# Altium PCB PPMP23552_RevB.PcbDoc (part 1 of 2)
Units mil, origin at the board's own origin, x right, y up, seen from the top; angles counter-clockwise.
Board outline 4950 x 3450 mil, 4 copper layers (Top Layer 1, Layer 2, Layer 3, Bottom Layer), stack 75.824 mil thick; 113 components, 58 nets, 311 pads, 148 vias.
Unrouted connection lines stored in the file: 10.
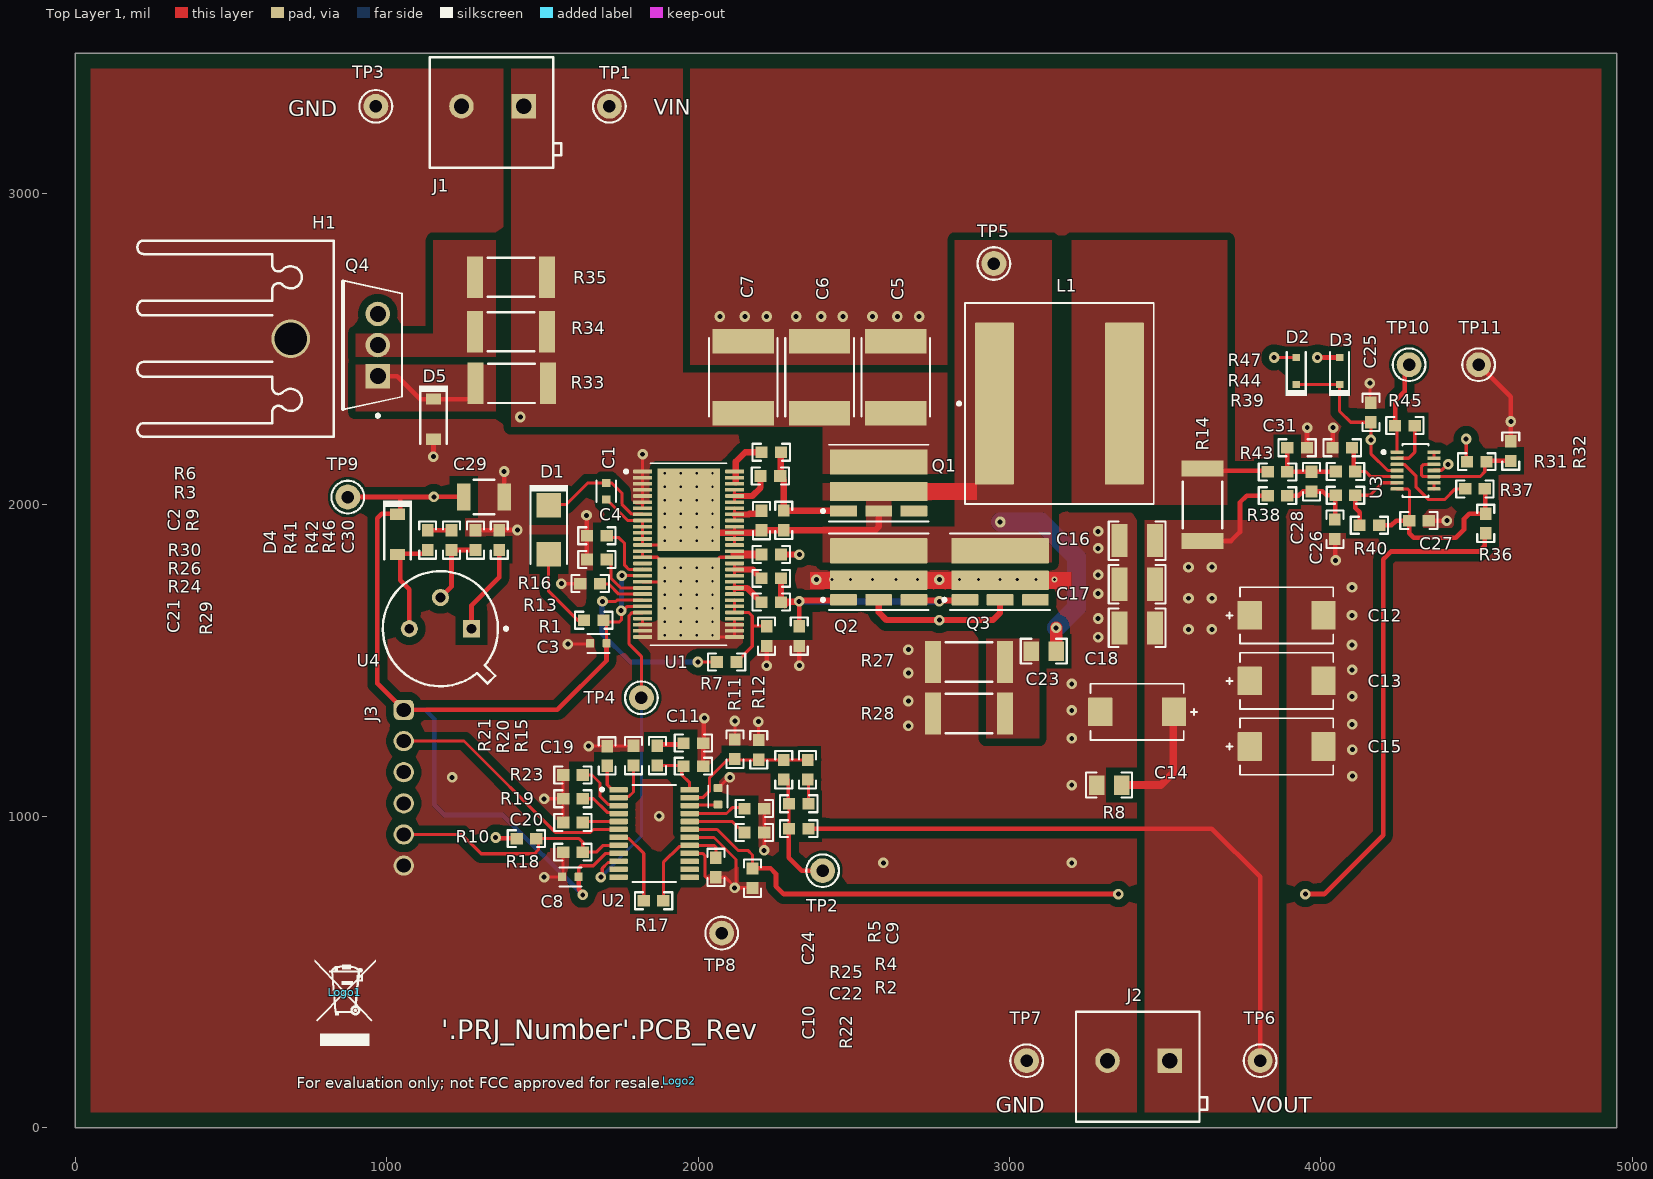
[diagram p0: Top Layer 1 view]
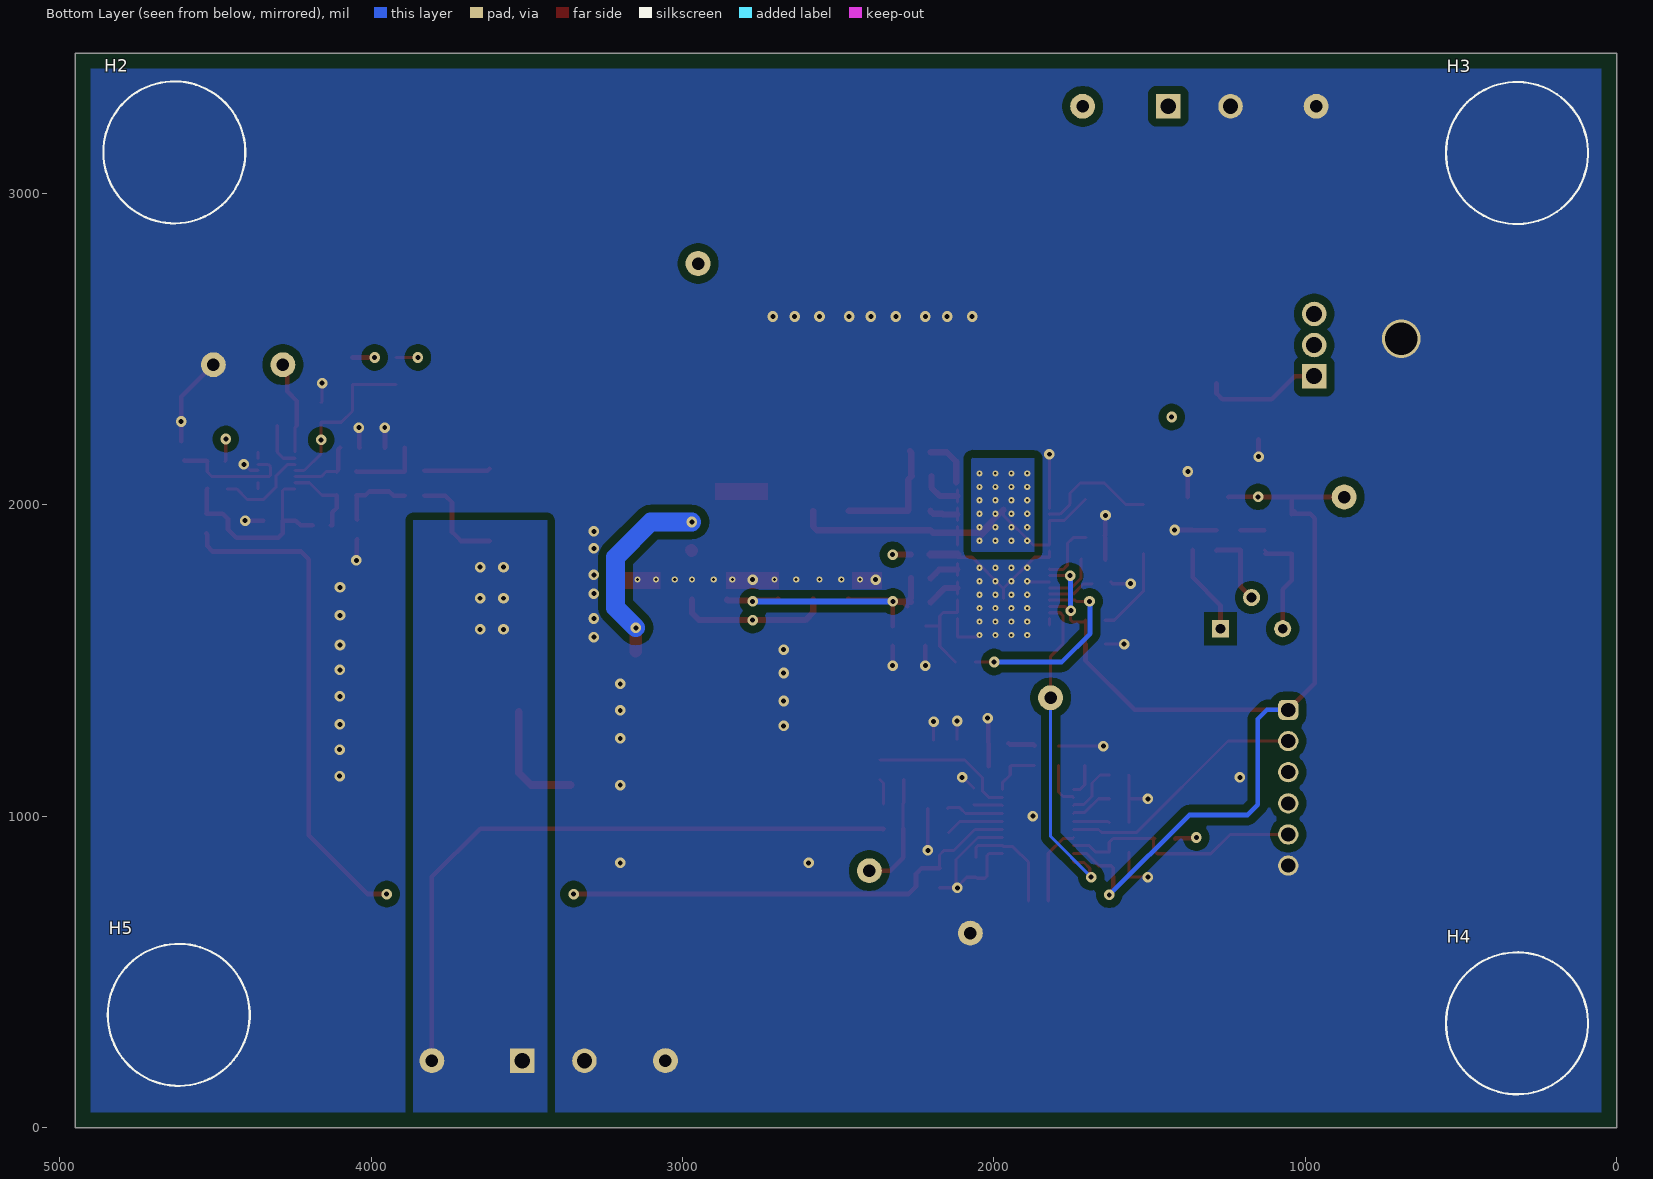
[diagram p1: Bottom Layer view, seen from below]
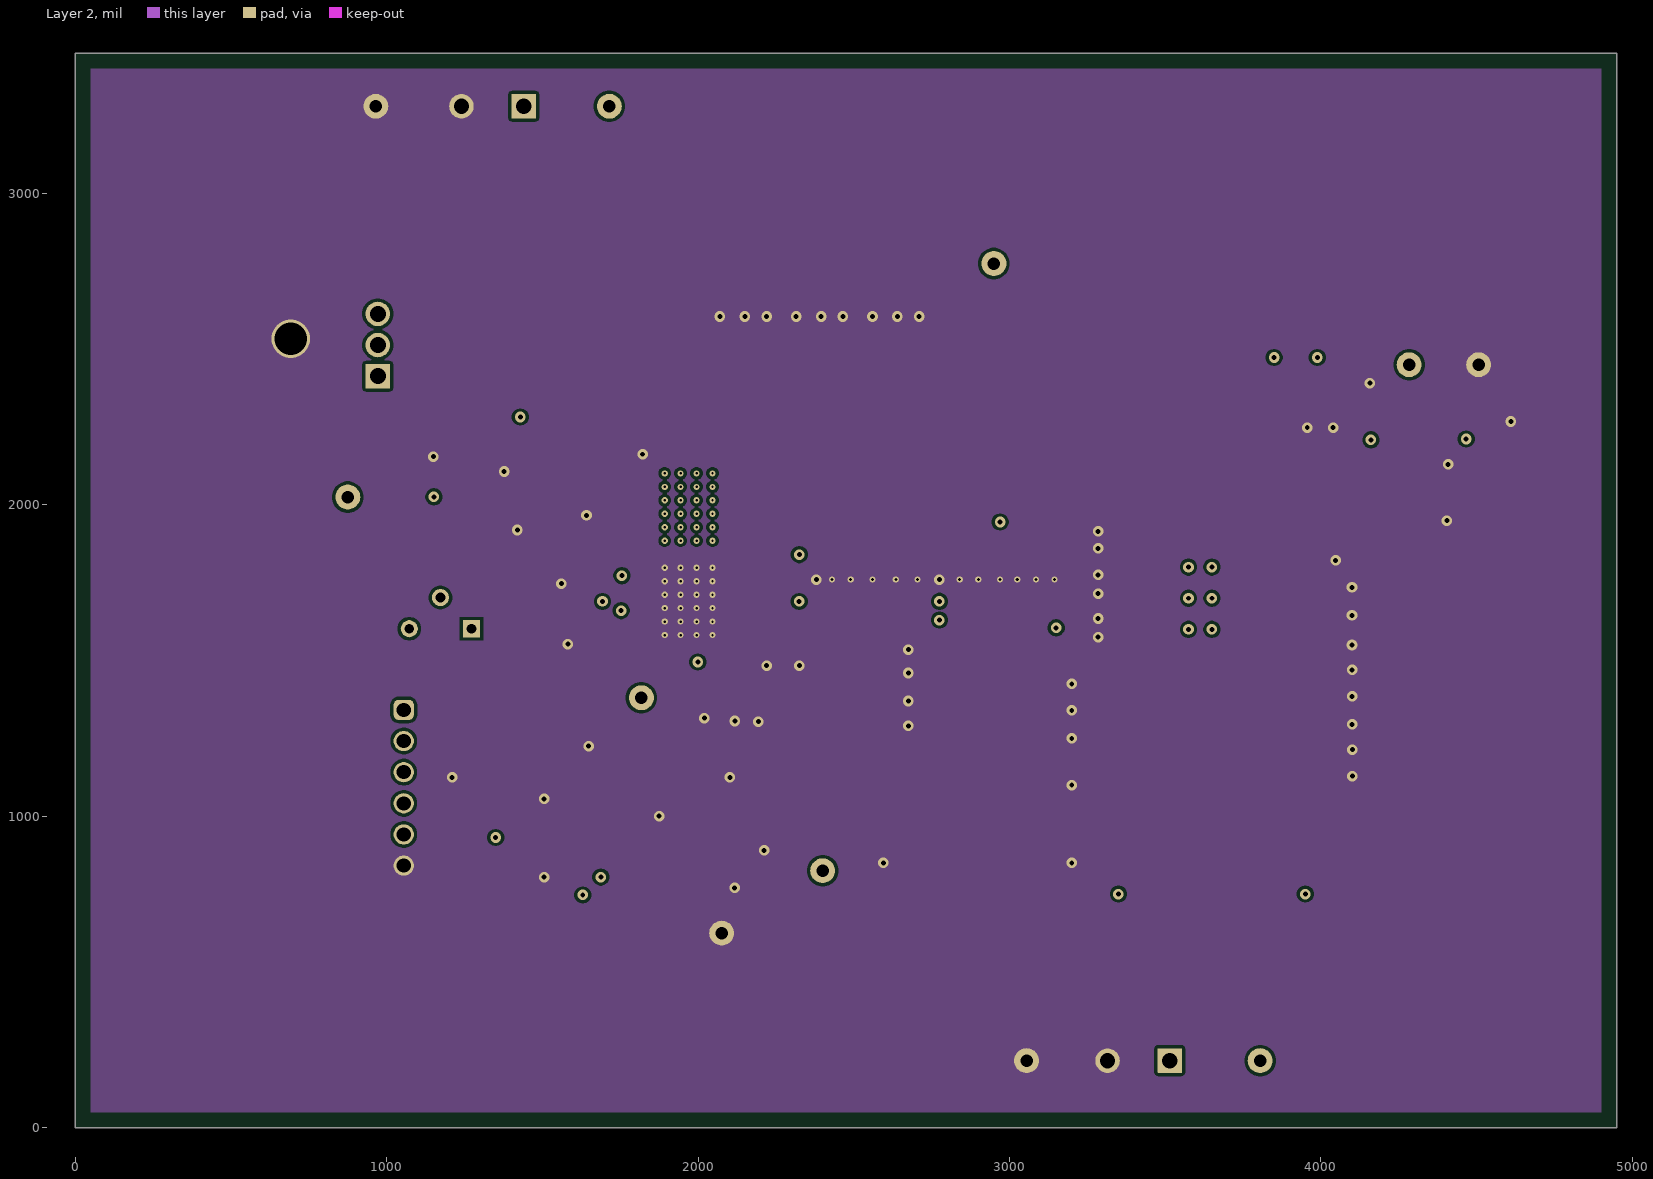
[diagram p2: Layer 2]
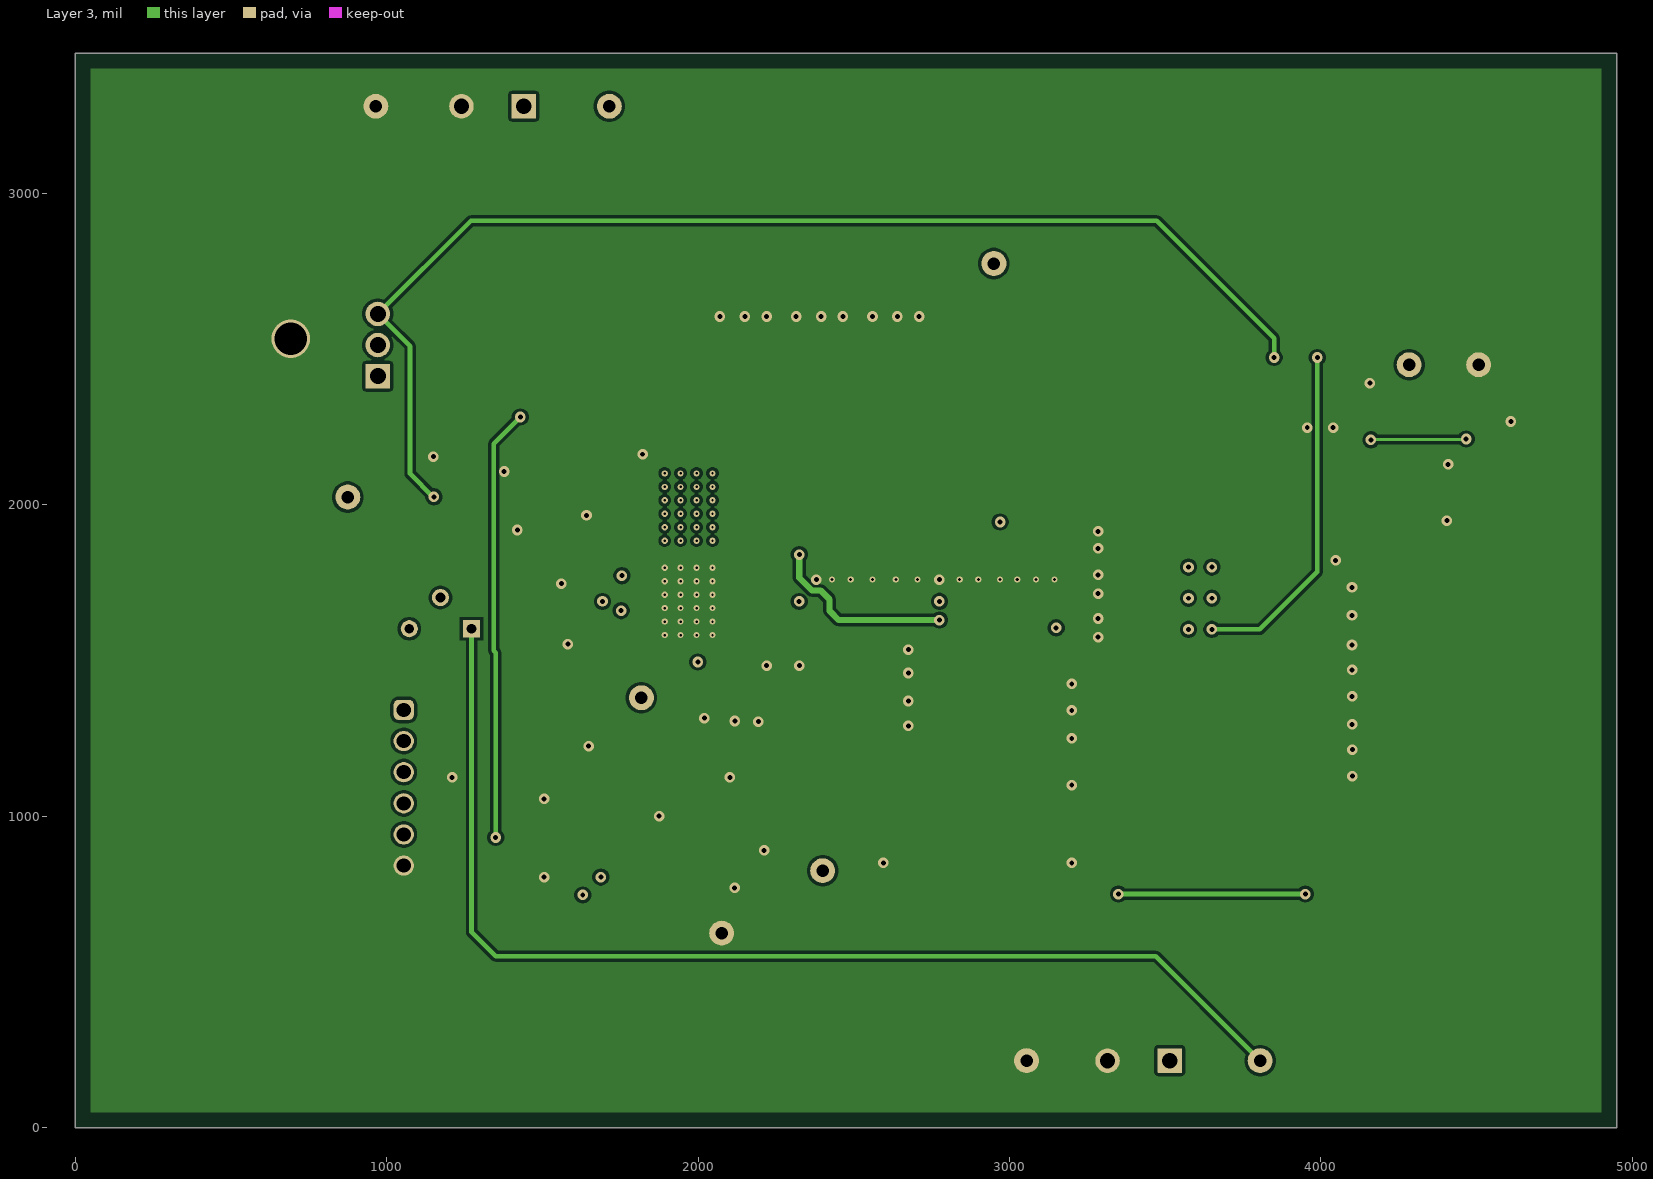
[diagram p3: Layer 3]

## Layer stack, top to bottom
Top Solder: solder mask 0.4, Solder Resist, Dk 3.5
Top Layer 1: signal copper 2.7559
Dielectric 1: prepreg 2.8, PP-006, Dk 4.1
Layer 2: signal copper 2.7559
Dielectric1: core 59.2, FR-4 High Tg, Dk 4.8
Layer 3: signal copper 2.7559
Dielectric 2: prepreg 2.8, PP-006, Dk 4.1
Bottom Layer: signal copper 2.7559
Bottom Solder: solder mask 0.4, Solder Resist, Dk 3.5

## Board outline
0,0 4950,0 4950,3450 0,3450

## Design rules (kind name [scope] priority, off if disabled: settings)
AcuteAngle [All] p1: minimum=4.50000000000000E+0001 checktracksonly=FALSE
AssemblyTestPointUsage [All] p1: valid=2
BoardOutlineClearance BoardOutlineClearance_MountingHoles [OnCopper and InComponentClass('Mounting Holes')] p1: gap=39.37 ignorepadtopadclearanceinfootprint=FALSE
BoardOutlineClearance BoardOutlineClearance_Poly [OnCopper and IsPoly] p2: gap=25 ignorepadtopadclearanceinfootprint=FALSE
BoardOutlineClearance [OnCopper and Not InComponentClass('Logo') and not InComponentClass('FiducialMark') and not InRegion(1000,500,4000,800) and not InPoly] p3: gap=40 ignorepadtopadclearanceinfootprint=FALSE
Clearance Clearance_4 [InNamedPolygon('TOP_LAYER_1_GND_P026')] p1: gap=25 ignorepadtopadclearanceinfootprint=FALSE
Clearance Clearance_3 [InNamedPolygon('BOTTOM_LAYER_GND_P023')] p2: gap=25 ignorepadtopadclearanceinfootprint=FALSE
Clearance Clearance_2 [InNamedPolygon('BOTTOM_LAYER_GND_P018')] p3: gap=25 ignorepadtopadclearanceinfootprint=FALSE
Clearance Clearance_1 [InNamedPolygon('TOP_LAYER_1_GND_P017')] p4: gap=25 ignorepadtopadclearanceinfootprint=FALSE
Clearance Clearance_Keepouts [((IsTrack Or IsArc) And Not InPoly) And IsFree and IsKeepOut vs ((IsTrack Or IsArc) And Not InPoly) And IsFree and IsKeepOut] p5: gap=0 ignorepadtopadclearanceinfootprint=FALSE
Clearance Clearance_Poly [InPolygon] p6: gap=10 ignorepadtopadclearanceinfootprint=TRUE
Clearance Clearance_FiducialMark [IsKeepOut and InComponentClass('FiducialMark') vs IsPad and InComponentClass('FiducialMark')] p7: gap=0 ignorepadtopadclearanceinfootprint=FALSE
Clearance [All] p8: gap=7.87 ignorepadtopadclearanceinfootprint=TRUE
ComponentClearance ComponentClearance_MountingHoles_FiducialMarks [InComponentClass('Mounting Holes') vs InComponentClass('FiducialMark')] p1: gap=50 collisioncheckmode=3 verticalgap=10 showdistances=FALSE
ComponentClearance ComponentClearance_Shunt [InComponentClass('Header') vs InComponentClass('Shunt')] p2: gap=0 collisioncheckmode=3 verticalgap=0 showdistances=FALSE
ComponentClearance ComponentClearance_Logo [InComponentClass('Logo')] p3: gap=30 collisioncheckmode=3 verticalgap=10 showdistances=FALSE
ComponentClearance ComponentClearance_ScrewToNut [(HasFootprint('NY PMS 440 0025 PH')) vs (HasFootprint('Keystone_1902C'))] p4: gap=5 collisioncheckmode=3 verticalgap=10 showdistances=FALSE
ComponentClearance ComponentClearance_MountingHoles [InComponentClass('Mounting Holes')] p5: gap=100 collisioncheckmode=3 verticalgap=100000 showdistances=FALSE
ComponentClearance ComponentClearance_SmallPassives [HasFootprint('0201*') or HasFootprint('0402*') or HasFootprint('0508') or HasFootprint('0603*') or HasFootprint('0612') or HasFootprint('0805*') or HasFootprint('0815*') or HasFootprint('0830*') or HasFootprint('1206*') or HasFootprint('1210*') or HasFootprint('1808*') or HasFootprint('1812*') or HasFootprint('1825*') or HasFootprint('2010*') or HasFootprint('2220*') or HasFootprint('2225*') or HasFootprint('2512*') or HasFootprint('2728*') or HasFootprint('3518*') vs HasFootprint('0201*') or HasFootprint('0402*') or HasFootprint('0508') or HasFootprint('0603*') or HasFootprint('0612') or HasFootprint('0805*') or HasFootprint('0815*') or HasFootprint('0830*') or HasFootprint('1206*') or HasFootprint('1210*') or HasFootprint('1808*') or HasFootprint('1812*') or HasFootprint('1825*') or HasFootprint('2010*') or HasFootprint('2220*') or HasFootprint('2225*') or HasFootprint('2512*') or HasFootprint('2728*') or HasFootprint('3518*')] p6: gap=14.96 collisioncheckmode=3 verticalgap=10 showdistances=FALSE
ComponentClearance ComponentClearance_THtoSMT [IsThruComponent vs IsSMTComponent] p7: gap=30 collisioncheckmode=3 verticalgap=30 showdistances=FALSE
ComponentClearance ComponentClearance_THtoTH [IsThruComponent vs IsThruComponent] p8: gap=20 collisioncheckmode=3 verticalgap=30 showdistances=FALSE
ComponentClearance [All] p9: gap=20 collisioncheckmode=3 verticalgap=10 showdistances=FALSE
DiffPairsRouting [All] p1: maxlimit=100 minlimit=10 mostfreqgap=10 toplayer_minwidth=15 toplayer_maxwidth=15 toplayer_prefwidth=15 midlayer1_minwidth=15 midlayer1_maxwidth=15 midlayer1_prefwidth=15 midlayer2_minwidth=15 midlayer2_maxwidth=15 midlayer2_prefwidth=15 bottomlayer_minwidth=15 bottomlayer_maxwidth=15 bottomlayer_prefwidth=15 maxuncoupledlength=1000
FabricationTestPointUsage TestPointUsage [All] p1: valid=2 allowmultiple=FALSE
FabricationTestpoint Testpoint [All] p1: side=3 testpointundercomponent=TRUE minsize=40 maxsize=100 preferedsize=60 minholesize=0 maxholesize=40 preferedholesize=32 testpointgrid=1 allowsidetop=TRUE allowsidebottom=TRUE usegrid=TRUE gridtolerance=0.01
FanoutControl Fanout_LCC [IsLCC] p1: bgadir=Out bgaviamode=Centered fanoutstyle=Auto fanoutdirection=Alternating viagrid=1 // Fanout_LCC (Default Rule)
FanoutControl Fanout_BGA [IsBGA] p2: bgadir=Out bgaviamode=Centered fanoutstyle=Auto fanoutdirection=Alternating viagrid=1 // Fanout_BGA (Default Rule)
FanoutControl Fanout_Default [All] p4: bgadir=Out bgaviamode=Centered fanoutstyle=Auto fanoutdirection=Alternating viagrid=1 // Fanout_Default (Default Rule)
FanoutControl Fanout_Small [(CompPinCount < 5)] p5: bgadir=Out bgaviamode=Centered fanoutstyle=Auto fanoutdirection=OutThenIn viagrid=1 // Fanout_Small (Default Rule)
HoleSize [All] p1: absolutevalues=TRUE maxlimit=251 minlimit=7.87 maxpercent=80.000 minpercent=20.000
MinimumAnnularRing MinimumAnnularRing_ThermalPadVias [IsVia and InAnyComponent] p1: minimumring=5.91
MinimumAnnularRing [All] p2: minimumring=7.87
MinimumSolderMaskSliver MinimumSolderMaskSliver_Logo [InComponentClass('Logo') vs InComponentClass('Logo')] p1: minsoldermaskwidth=0.7
MinimumSolderMaskSliver [All] p2: minsoldermaskwidth=3.94
PlaneConnect [All] p1: planeconnectstyle=Relief reliefexpansion=10 reliefentries=4 reliefconductorwidth=10 reliefairgap=10
PolygonConnect [All] p1: connectstyle=Direct reliefconductorwidth=10 reliefentries=4 polygonreliefangle="90 Angle" airgapwidth=10
RoutingVias ThermalPadVias [IsVia and InAnyComponent] p1: holewidth=7.87 width=19.68 viastyle="Through Hole" minholewidth=7.87 minwidth=19.68 maxholewidth=12.99 maxwidth=23.62
RoutingVias [All] p2: holewidth=16 width=34 viastyle="Through Hole" minholewidth=7.87 minwidth=24 maxholewidth=40 maxwidth=65
SilkToBoardRegionClearance [Not ((IsComment or IsDesignator) And (Hide <> 'False')) and not InRegion(1000,500,4000,800)] p1:
SilkToSilkClearance SilkToSilkClearance_Pb-FreeLogo [(HasFootprint('Pb-Free_Overlay_Medium') OR HasFootprint('Pb-Free_Overlay_Small')) vs (HasFootprint('Pb-Free_Overlay_Medium') OR HasFootprint('Pb-Free_Overlay_Small'))] p1: silktosilkclearance=0
SilkToSilkClearance [All] p2: silktosilkclearance=3.94
SilkToSolderMaskClearance SilkToComponentPadClearance [(IsPad or IsFill or IsRegion) and InAnycomponent] p1: minsilkscreentomaskgap=5 clearancetoexposedcopper=TRUE
SilkToSolderMaskClearance "Silk to Solder Mask Opening" [All] p2: minsilkscreentomaskgap=3.94 clearancetoexposedcopper=FALSE
SolderMaskExpansion [All] p1: expansion=1.97 istentingtop=FALSE
UnRoutedNet [All] p1: checkbadconnections=TRUE
Width [All] p1: maxlimit=100 minlimit=6 preferedwidth=10 checkconnectedcopper=TRUE
14 further rules are at their usual default settings.

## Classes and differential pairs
component class Header: J3

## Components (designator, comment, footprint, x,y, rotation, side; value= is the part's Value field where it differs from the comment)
C1 "GCJ188R71E104KA12D" FP-GCJ188R71E104KA12D_0603-MFG 1705.39,2043.54 r270 top value=100nF
C2 "885012206026" 0603 2203.58,1949.62 r90 top value=1uF
C3 "GCJ188R71E104KA12D" FP-GCJ188R71E104KA12D_0603-MFG 1680,1555 r0 top value=100nF
C4 "885012206026" 0603 1675.08,1900.78 r180 top value=1uF
C5 "CKG57NX7T2E335M500JH" CKG57N 2635,2410 r90 top value=3.3uF
C6 "CKG57NX7T2E335M500JH" CKG57N 2390,2410 r90 top value=3.3uF
C7 "CKG57NX7T2E335M500JH" CKG57N 2145,2410 r90 top value=3.3uF
C8 "GCJ188R71E104KA12D" FP-GCJ188R71E104KA12D_0603-MFG 1590,805 r0 top value=100nF
C9 "C0603X102K5RACTU" 0603 2351.65,1149.21 r90 top value=1000pF
C10 "885012206026" 0603 2057.09,835.39 r270 top value=1uF
C11 "C0603C223K5RACTU" 0603 1985,1234.85 r180 top value=0.022uF
C12 "T521X226M063ATE075" FP-T521X226M063ATE075_2917-MFG 3890,1645 r180 top value=22µF
C13 "T521X226M063ATE075" FP-T521X226M063ATE075_2917-MFG 3890,1434.44 r180 top value=22µF
C14 "T521X226M063ATE075" FP-T521X226M063ATE075_2917-MFG 3410,1335 r0 top value=22µF
C15 "T521X226M063ATE075" FP-T521X226M063ATE075_2917-MFG 3890,1223.88 r180 top value=22µF
C16 "GXM32ER71H106KA10" 1210 3410,1885 r180 top value=10uF
C17 "GXM32ER71H106KA10" 1210 3410,1745 r180 top value=10uF
C18 "GXM32ER71H106KA10" 1210 3410,1605 r180 top value=10uF
C19 "GCM1885C1H680JA16D" 0603 1985,1160.79 r180 top value=68pF
C20 "885012206086" 0603 1598.09,979.61 r180 top value=3300pF
C21 "885012206026" 0603 2220,1578.38 r90 top value=1uF
C22 "CGA3E3X7R1H474K080AE" 0603 2180.84,947.88 r0 top value=0.47uF
C23 "08052A331JAT2A" 0805_HV 3110,1530 r0 top value=330pF
C24 "GCJ188R71E104KA12D" FP-GCJ188R71E104KA12D_0603-MFG 2063.88,1063.96 r270 top value=100nF
C25 "CGA3E1X7R1V105K080AE" 0603 4160.78,2296.68 r270 top value=1uF
C26 "C0603C101F5GACTU" 0603 4045.15,1921.5 r90 top value=100pF
C27 "C0603C101F5GACTU" 0603 4315,1949.37 r0 top value=100pF
C28 "C0603C101F5GACTU" 0603 3970,2074.37 r90 top value=100pF
C29 "C1210C475K5RACAUTO" 1210_280 1312.33,2025 r0 top value=4.7uF
C30 "HMK107B7104KAHT" 0603 1361.57,1886.72 r90 top value=0.1uF
C31 "C0603C101F5GACTU" 0603 3923.77,2183.52 r0 top value=100pF
D1 "SS1200-LTP" SMA 1520.02,1919.69 r270 top value=200V
D2 "PMEG6010CEJ,115" SOD-323F 3920.76,2430.01 r90 top value=60V
D3 "PMEG6010CEJ,115" SOD-323F 4060.15,2430.01 r90 top value=60V
D4 "BAT54T1G" SOD-123 1034.75,1905.42 r270 top value=30V
D5 "MMSZ4698T1G" SOD-123 1150,2275 r270 top value=11V
H1 "V7700W" ASMN_V7700W 691.65,2533.79 r90 top
H2 "SJ-5303 (CLEAR)" Bumpon_SJ5003Transparent 4632,3132 r180 bottom
H3 "SJ-5303 (CLEAR)" Bumpon_SJ5003Transparent 320,3130 r180 bottom
H4 "SJ-5303 (CLEAR)" Bumpon_SJ5003Transparent 320,335 r180 bottom
H5 "SJ-5303 (CLEAR)" Bumpon_SJ5003Transparent 4618,362 r180 bottom
J1 "ED120/2DS" On-Shore_ED120_2DS 1340,3280 r180 top
J2 "ED120/2DS" On-Shore_ED120_2DS 3415,215 r180 top
J3 "61300611121" WURTH_61300611121 1054.75,1091.4 r270 top
L1 "XAL1513-153MED" FP-XAL1513-153MED_SMT_IND_15MM2_16MM2-MFG 3160,2325 r0 top value=15uH
Logo1 "WEEE logo" WEEE_Minimum 865,435 r0 top
Logo2 "FCC disclaimer" FCC_disclaimer 1939.2,150 r0 top
Q1 "EPC7020GSH" FP-EPC7020GSH_FSMD-G-MFG 2580,2070 r180 top
Q2 "EPC7020GSH" FP-EPC7020GSH_FSMD-G-MFG 2580,1785 r180 top
Q3 "EPC7020GSH" FP-EPC7020GSH_FSMD-G-MFG 2970,1785 r180 top
Q4 "BUX85G" FP-BUX85G_TO-220-3-MFG 954.38,2513.19 r180 top value=450V
R1 "RC0603FR-07100RL" 0603 1664.96,1629.22 r180 top value=100
R2 "RC0603FR-0710RL" 0603 2323.15,960.05 r0 top value=10.0
R3 "RC0603FR-071RL" 0603 2232.12,2092.54 r0 top value=1.00
R4 "RC0603FR-07511RL" 0603 2323.15,1040.06 r180 top value=511
R5 "RC0603FR-0749K9L" 0603 2275.15,1149.21 r270 top value=49.9k
R6 "RC0603FR-071RL" 0603 2235.07,2168.98 r0 top value=1.00
R7 "M55342K12B10E0T" 0603 2091.54,1495.3 r0 top value=10.0k
R8 "CRCW080527K0JNEA" 0805_HV 3320,1100 r180 top value=27k
R9 "M55342K12B10E0T" 0603 2275,1950 r90 top value=10.0k
R10 "RC0603FR-07562KL" 0603 1448.81,928.01 r180 top value=562k
R11 "RC0603FR-073K01L" 0603 2118.25,1215.16 r270 top value=3.01k
R12 "RC0603FR-071K78L" 0603 2194.69,1213.2 r270 top value=1.78k
R13 "RC0603FR-0712K7L" 0603 1653.43,1746.93 r0 top value=12.7k
R14 "ERJ-M1WSF4M0U" 2512 3620,2000 r270 top value=0.004
R15 "RC0603FR-072K8L" 0603 1869.33,1194.5 r90 top value=2.80k
R16 "ERJ-3EKF2002V" 0603 1675.08,1824.28 r0 top value=20.0k
R17 "RMCF0603ZT0R00" 0603 1856.94,728.53 r0 top value=0
R18 "M55342K12B10E0T" 0603 1598.09,884.48 r0 top value=10.0k
R19 "M55342K12B10E0T" 0603 1598.09,1056.05 r180 top value=10.0k
R20 "M55342K12B10E0T" 0603 1792.56,1194.5 r90 top value=10.0k
R21 "RC0603FR-07422KL" 0603 1707.91,1193.51 r270 top value=422k
R22 "RC0603FR-07100KL" 0603 2174.88,800.94 r90 top value=100k
R23 "M55342K12B10E0T" 0603 1598.09,1132.48 r180 top value=10.0k
R24 "RC0603FR-071RL" 0603 2235.07,1687.53 r0 top value=1.00
R25 "RC0603FR-07100KL" 0603 2180.84,1024.38 r180 top value=100k
R26 "RC0603FR-071RL" 0603 2235.07,1763.96 r0 top value=1.00
R27 "CRCW251220R0JNEG" 2512 2870,1495 r180 top value=20
R28 "CRCW251220R0JNEG" 2512 2870,1330 r180 top value=20
R29 "M55342K12B10E0T" 0603 2325,1578.38 r90 top value=10.0k
R30 "RMCF0603ZT0R00" 0603 2235.07,1840.47 r180 top value=0
R31 "RC0603FR-0710ML" 0603 4500.85,2138.62 r0 top value=10.0Meg
R32 "RC0603FR-0710ML" 0603 4610,2172.62 r270 top value=10.0Meg
R33 "CRCW251251K0JNEG" 2512 1401.14,2390 r180 top value=51k
R34 "CRCW25122K00FKEG" 2512 1399.04,2555.63 r0 top value=2.00k
R35 "CRCW25122K00FKEG" 2512 1399,2730.63 r0 top value=2.00k
R36 "RMCF0603ZT0R00" 0603 4529.45,1940.2 r90 top value=0
R37 "RMCF0603ZT0R00" 0603 4495,2051.26 r180 top value=0
R38 "RG1608P-103-B-T5" 0603 3860.78,2029.43 r0 top value=10.0k
R39 "RG1608P-103-B-T5" 0603 4079.15,2030.65 r0 top value=10.0k
R40 "RT0603BRD07200KL" 0603 4156,1934.38 r0 top value=200k
R41 "RC0603FR-0715RL" 0603 1131.48,1886.72 r270 top value=15.0
R42 "RC0603FR-07274RL" 0603 1207.92,1886.72 r270 top value=274
R43 "RG1608P-103-B-T5" 0603 3860.78,2105.87 r0 top value=10.0k
R44 "RG1608P-103-B-T5" 0603 4079.15,2107.09 r0 top value=10.0k
R45 "RMCF0603ZT0R00" 0603 4270,2254.37 r0 top value=0
R46 "RC0603FR-072K43L" 0603 1285.07,1886.72 r270 top value=2.43k
R47 "RT0603BRD07200KL" 0603 4068.54,2183.52 r0 top value=200k
TP1 "5000" Keystone5000 1715,3280 r90 top
TP2 "5002" Keystone5002 2400,825 r90 top
TP3 "5001" Keystone5001 965,3280 r90 top
TP4 "5002" Keystone5002 1817.92,1380.4 r90 top
TP5 "5000" Keystone5000 2950,2775 r180 top
TP6 "5000" Keystone5000 3805,215 r90 top
TP7 "5001" Keystone5001 3055,215 r90 top
TP8 "5001" Keystone5001 2075.79,624.6 r90 top
TP9 "5000" Keystone5000 875,2025 r90 top
TP10 "5000" Keystone5000 4283.5,2450 r180 top
TP11 "5001" Keystone5001 4506.75,2450 r180 top
U1 "TPS7H6005MDCATSEP" DCA0056M-MFG 1969.49,1841.35 r0 top
U2 "TPS7H5006MPWTSEP" PW0024A-MFG 1858.75,944.66 r0 top
U3 "OPA4H199MDYYTSEP" DYY0014A-MFG 4304.06,2110.32 r0 top
U4 "LM117HRLQMLV" NDT0003A 1172.47,1602.15 r180 top

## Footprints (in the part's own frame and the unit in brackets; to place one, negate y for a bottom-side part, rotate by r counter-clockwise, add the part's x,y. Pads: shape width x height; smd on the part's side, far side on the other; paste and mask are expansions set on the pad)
0603 [mm] "0603 from SM-752 data"
  rect 1x0.95 smd: 1(-0.8,0) 2(0.8,0)
  silkscreen extent -1.52,-0.69 1.52,0.69, body extent -0.87,-0.47 0.87,0.47, height 1
0805_HV [mil] "0805 with 30mil clearance between pads"
  rect 50x63 smd: 1(-40,0) 2(40,0)
  silkscreen extent -74,-40 74,40, body extent -43,-29 43,29, height 57
1210 [mm] "1210 from SM-752 data"
  rect 1.3x2.7 smd: 1(-1.45,0) 2(1.45,0)
  silkscreen extent -2.32,-1.57 2.32,1.57, body extent -1.7,-1.35 1.7,1.35, height 1.35
1210_280 [mm] "SMD, 2-Leads, Body 3.6x2.8mm, Height 2.8mm"
  rect 1.1x2.2 smd: 1(-1.65,0) 2(1.65,0)
  silkscreen extent -0.84,-1.4 0.84,1.4, body extent -1.8,-1.4 1.8,1.4, height 2.8
2512 [mm] "Chip Resistor, Body 6.3x3.2mm, IPC Medium Density"
  rect 1.3x3.4 smd: 1(-2.95,0) 2(2.95,0)
  silkscreen extent -1.9,-1.6 1.9,1.6, body extent -3.22,-1.67 3.22,1.67, height 0.71
ASMN_V7700W [mm] "Heat Sink SOT-32, TO-220"
  round 3.15 hole 2.65: 1(0,0)
  silkscreen extent -8,-3.5 8,12.5, body extent -8,-3.5 8,12.5, height 25
Bumpon_SJ5003Transparent [mil] "3M Hemispherical Bumpon transparent"
  round 1 on Mech4: 0(0,0)
  silkscreen extent -228,-228 228,228, body extent -218,-218 219,218, height 197
CKG57N [mm] "Chip Capacitor, Body 6.0x5.0x5.0mm,"
  rect 2x5 smd: 1(-2.95,0) 2(2.95,0)
  silkscreen extent -3.2,-2.8 3.2,2.8, body extent -3.3,-2.75 3.3,2.75, height 5.5
DCA0056M-MFG [mm]
  rrect33% 1.55x0.3 smd paste+0 mask+0: 1(-3.75,6.75) 2(-3.75,6.25) 3(-3.75,5.75) 4(-3.75,5.25) 5(-3.75,4.75) 6(-3.75,4.25) 7(-3.75,3.75) 8(-3.75,3.25) 9(-3.75,2.75) 10(-3.75,2.25) 11(-3.75,1.75) 12(-3.75,1.25) 13(-3.75,0.75) 14(-3.75,0.25) 15(-3.75,-0.25) 16(-3.75,-0.75) 17(-3.75,-1.25) 18(-3.75,-1.75) 19(-3.75,-2.25) 20(-3.75,-2.75) 21(-3.75,-3.25) 22(-3.75,-3.75) 23(-3.75,-4.25) 24(-3.75,-4.75) 25(-3.75,-5.25) 26(-3.75,-5.75) 27(-3.75,-6.25) 28(-3.75,-6.75) 29(3.75,-6.75) 30(3.75,-6.25) 31(3.75,-5.75) 32(3.75,-5.25) 33(3.75,-4.75) 34(3.75,-4.25) 35(3.75,-3.75) 36(3.75,-3.25) 37(3.75,-2.75) 38(3.75,-2.25) 39(3.75,-1.75) 40(3.75,-1.25) 41(3.75,-0.75) 42(3.75,-0.25) 43(3.75,0.25) 44(3.75,0.75) 45(3.75,1.25) 46(3.75,1.75) 47(3.75,2.25) 48(3.75,2.75) 49(3.75,3.25) 50(3.75,3.75) 51(3.75,4.25) 52(3.75,4.75) 53(3.75,5.25) 54(3.75,5.75) 55(3.75,6.25) 56(3.75,6.75)
  rrect2% 5.1x6.75 smd paste-1000 mask-1000: 57(0,3.625) 58(0,-3.625)
  silkscreen extent -5.22,-7.42 3.1,7.42, body extent -4.62,-7.15 4.62,7.15, height 0.25
DYY0014A-MFG [mm]
  rrect33% 1.05x0.3 smd paste+0 mask+0: 1(-1.5,1.5) 2(-1.5,1) 3(-1.5,0.5) 4(-1.5,0) 5(-1.5,-0.5) 6(-1.5,-1) 7(-1.5,-1.5) 8(1.5,-1.5) 9(1.5,-1) 10(1.5,-0.5) 11(1.5,0) 12(1.5,0.5) 13(1.5,1) 14(1.5,1.5)
  silkscreen extent -2.72,-2.15 1.05,2.15, body extent -1.63,-2.1 1.63,2.1, height 1.1
FCC_disclaimer [mil]
FP-BUX85G_TO-220-3-MFG [mm]
  rrect5% 2x2 hole 1.3 paste-1000 mask+0: 1(-0.433,2.54)
  round 2 hole 1.3 paste-1000 mask+0: 2(-0.433,0) 3(-0.433,-2.54)
  silkscreen extent -2.41,-5.27 2.41,5.89, body extent -2.51,-5.37 2.51,5.37, height 0.25
FP-EPC7020GSH_FSMD-G-MFG [mm]
  rrect11% 2.184x0.914 smd paste+0 mask+0: 1(2.87,2.286) 2(-2.87,2.286) 5(0,2.286)
  rrect5% 7.95x2.057 smd paste+0 mask+0: 3(0,-1.714)
  rrect6% 7.95x1.575 smd paste+0 mask+0: 4(0,0.686)
  silkscreen extent -4.08,-3.13 4.67,3.13, body extent -4.18,-2.96 4.18,2.96, height 0.25
FP-GCJ188R71E104KA12D_0603-MFG [mm]
  rrect15% 0.65x0.7 smd paste+0 mask+0: 1(-0.675,0) 2(0.675,0)
  silkscreen extent -0.9,-0.79 0.9,0.77, body extent -0.8,-0.4 0.8,0.4, height 0.9
FP-T521X226M063ATE075_2917-MFG [mm] "Recommended Land Pattern"
  rrect5% 1.99x2.33 smd paste+0 mask+0: 1(-3.01,0) 2(3.01,0)
  silkscreen extent -3.8,-2.3 4.9,2.3, body extent -4.13,-2.42 4.13,2.42, height 0.25
FP-XAL1513-153MED_SMT_IND_15MM2_16MM2-MFG [mm]
  rrect3% 3.18x13.2 smd paste+0 mask+0: 1(-5.3,0) 2(5.3,0)
  silkscreen extent -8.3,-8.2 7.7,8.2, body extent -7.8,-8.3 7.8,8.3, height 0.25
Keystone5000 [mil] "For Keystone 500x miniature loop terminals"
  round 80 hole 40: 1(0,0)
  silkscreen extent -52,-52 52,52, body extent -49,-49 49,49, height 182
Keystone5001 [mil] "For Keystone 500x miniature loop terminals"
  round 80 hole 40: 1(0,0)
  silkscreen extent -52,-52 52,52, body extent -49,-49 49,49, height 182
Keystone5002 [mil] "For Keystone 500x miniature loop terminals"
  round 80 hole 40: 1(0,0)
  silkscreen extent -52,-52 52,52, body extent -49,-49 49,49, height 182
NDT0003A [mm] "Can; 3 Leads; Pin Circle Dia. 5.08 mm; Lead Dia. 0.48 mm (max)"
  rect 1.4x1.4 hole 0.8: 1(-2.54,0)
  round 1.4 hole 0.8: 2(0,-2.54) 3(2.54,0)
  silkscreen extent -5.48,-4.69 4.69,4.69, body extent -4.69,-4.69 4.69,4.69, height 4.7
On-Shore_ED120_2DS [mm] "ONSHORE"
  rrect5% 2x2 hole 1.25: 1(-2.54,0)
  round 2 hole 1.25: 2(2.54,0)
  silkscreen extent -5.6,-4 5.12,5, body extent -5.78,-4 5.08,5, height 13
PW0024A-MFG [mm]
  rrect22% 1.5x0.45 smd paste+0 mask+0: 1(-2.9,3.575) 2(-2.9,2.925) 3(-2.9,2.275) 4(-2.9,1.625) 5(-2.9,0.975) 6(-2.9,0.325) 7(-2.9,-0.325) 8(-2.9,-0.975) 9(-2.9,-1.625) 10(-2.9,-2.275) 11(-2.9,-2.925) 12(-2.9,-3.575) 13(2.9,-3.575) 14(2.9,-2.925) 15(2.9,-2.275) 16(2.9,-1.625) 17(2.9,-0.975) 18(2.9,-0.325) 19(2.9,0.325) 20(2.9,0.975) 21(2.9,1.625) 22(2.9,2.275) 23(2.9,2.925) 24(2.9,3.575)
  silkscreen extent -4.37,-3.95 1.78,3.95, body extent -3.75,-4.2 3.75,4.2, height 0.25
SMA [mm] "Molded Diode, 2-Leads, Body 4.3x2.6mm, IPC Medium Density, based on OnSemi component dimensions and land pattern"
  rect 2x2 smd: 1(-2,0) 2(2,0)
  silkscreen extent -3.66,-1.57 2.79,1.57, body extent -2.6,-1.3 2.6,1.3, height 2.42
SOD-123 [mm] "On Semi recommended land pattern"
  rect 0.915x1.22 smd: 1(-1.637,0) 2(1.637,0)
  silkscreen extent -2.74,-1.17 2.03,1.16, body extent -1.93,-0.9 1.93,0.9, height 1.35
SOD-323F [mm] "NXP recommended land pattern"
  rect 0.6x0.6 smd paste-0.05: 1(-1.1,0) 2(1.1,0)
  silkscreen extent -2.06,-0.86 1.53,0.86, body extent -1.35,-0.67 1.35,0.68, height 0.79
WEEE_Minimum [mil] "WEEElie bin"
  silkscreen extent -95,-172 99,104
WURTH_61300611121 [mm] "Header, 2.54mm, 6x1, TH"
  rrect50% 1.65x1.65 hole 1.15: 1(-6.35,0)
  round 1.65 hole 1.15: 2(-3.81,0) 3(-1.27,0) 4(1.27,0) 5(3.81,0) 6(6.35,0)
  body extent -7.62,-1.27 7.62,1.27, height 8.54

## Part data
C1 C3 C8 C24: library part CMP-0095670-2, "Cap Ceramic 0.1uF 25V X7R 10% Pad SMD 0603 Soft Termination +125°C Automotive T/R", Manufacturer=Murata, Operating Temperature Range="-55°C to +125°C", TempCo=15%, Temperature Characteristic=X7R, Tolerance_%=10%, ValueDisplayed=0.1uF
C2 C4 C10 C21: library part CMP-0064932-4, "CAP, CERM, 1 uF, 10 V,+/- 10%, X7R, 0603", Cap_Case=0603, Manufacturer="Wurth Elektronik", Supplier Part Number 1=732-7945-1-ND, TempCo=X7R, Tolerance_%=10%, Value1=Unknown, Value2=10V, ValueDisplayed=1uF
C5 C6 C7: library part CMP-0009427-2, "CAP, CERM, 3.3 uF, 250 V, +/- 20%, X7T, AEC-Q200 Grade 1, 6x5x5mm", Cap_Case=2220, Manufacturer=TDK, Supplier Part Number 1=445-7108-1-ND, TempCo=X7T, Tolerance_%=20%, Value1=Unknown, Value2=250V, ValueDisplayed=3.3uF
C9: library part CMP-0006976-5, "CAP, CERM, 1000 pF, 50 V, +/- 10%, X7R, 0603", Cap_Case=0603, Manufacturer=Kemet, Supplier Part Number 1=399-5348-1-ND, TempCo=X7R, Tolerance_%=10%, Value1=Unknown, Value2=50V, ValueDisplayed=1000pF
C11: library part CMP-0006901-4, "CAP, CERM, 0.022 uF, 50 V, +/- 10%, X7R, 0603", Cap_Case=0603, Manufacturer=Kemet, Supplier Part Number 1=399-1280-1-ND, TempCo=X7R, Tolerance_%=10%, Value1=Unknown, Value2=50V, ValueDisplayed=0.022uF
C12 C13 C14 C15: library part CMP-0124532-1, "Cap Tant Polymer 22uF 63VDC X CASE 20% (7.3 X 4.3 X 4mm) SMD 7343-43 0.075 Ohm 125C T/R", Digikey Part Number=399-14801-1-ND, Leakage Current=138.6uA, Manufacturer=KEMET, Mouser Part Number=80-T521X226M63ATE075, Operating Temperature Range="-55°C to +125°C", Tolerance_%=20%, ValueDisplayed=22uF
C16 C17 C18: library part CMP-0861001-1, "CAP, CERM, 10 µF, 50 V,+/- 10%, X7R, 1210", Cap_Case=1210, Manufacturer=MuRata, TempCo=X7R, Tolerance_%=10%, Value2=50V, ValueDisplayed=10µF
C19: library part CMP-0007129-4, "CAP, CERM, 68 pF, 50 V, +/- 5%, C0G/NP0, AEC-Q200 Grade 1, 0603", Cap_Case=0603, Manufacturer=MuRata, Supplier Part Number 1=490-4961-1-ND, TempCo=C0G/NP0, Tolerance_%=5%, Value1=Unknown, Value2=50V, ValueDisplayed=68pF
C20: library part CMP-0077942-1, "CAP, CERM, 3300 pF, 50 V,+/- 10%, X7R, 0603", Cap_Case=0603, Manufacturer="Wurth Elektronik", Supplier Part Number 1=732-8004-1-ND, TempCo=X7R, Tolerance_%=10%, Value2=50V, ValueDisplayed=3300pF
C22: library part CMP-0007097-4, "CAP, CERM, 0.47 uF, 50 V, +/- 10%, X7R, AEC-Q200 Grade 1, 0603", Cap_Case=0603, Manufacturer=TDK, Supplier Part Number 1=445-172475-1-ND, TempCo=X7R, Tolerance_%=10%, Value1=Unknown, Value2=50V, ValueDisplayed=0.47uF
C23: library part CMP-0080810-1, "CAP, CERM, 330 pF, 200 V,+/- 5%, C0G/NP0, 0805", Cap_Case=0805, Manufacturer=AVX, Supplier Part Number 1=478-1275-1-ND, TempCo=C0G/NP0, Tolerance_%=5%, Value2=200V, ValueDisplayed=330pF
C25: library part CMP-0081259-1, "CAP, CERM, 1 µF, 35 V,+/- 10%, X7R, AEC-Q200 Grade 1, 0603", Cap_Case=0603, Manufacturer=TDK, Supplier Part Number 1=445-174339-1-ND, TempCo=X7R, Tolerance_%=10%, Value2=35V, ValueDisplayed=1µF
C26 C27 C28 C31: library part CMP-0080091-1, "CAP, CERM, 100 pF, 50 V,+/- 1%, C0G/NP0, 0603", Cap_Case=0603, Manufacturer=Kemet, Supplier Part Number 1=399-7819-1-ND, TempCo=C0G/NP0, Tolerance_%=1%, Value2=50V, ValueDisplayed=100pF
C29: library part CMP-0079604-1, "CAP, CERM, 4.7 µF, 50 V,+/- 10%, X7R, AEC-Q200 Grade 1, 1210", Cap_Case=1210, Manufacturer=Kemet, Supplier Part Number 1=399-7049-1-ND, TempCo=X7R, Tolerance_%=10%, Value2=50V, ValueDisplayed=4.7µF
C30: library part CMP-0081011-1, "CAP, CERM, 0.1 µF, 100 V,+/- 10%, X7R, AEC-Q200 Grade 1, 0603", Cap_Case=0603, Manufacturer="Taiyo Yuden", Supplier Part Number 1=587-6009-1-ND, TempCo=X7R, Tolerance_%=10%, Value2=100V, ValueDisplayed=0.1µF
D1: library part CMP-0028981-2, "Diode, Schottky, 200 V, 1 A, SMA", Manufacturer="Micro Commercial Components", Value1=1A, Value2=0.92V
D2 D3: library part CMP-0077011-2, "Diode, Schottky, 60 V, 1 A, SOD-323F", Manufacturer=Nexperia, Value1=1A, Value2=0.66V
D4: library part CMP-0028457-2, "Diode, Schottky, 30 V, 0.2 A, SOD-123", Manufacturer="ON Semiconductor", Value1=0.2A, Value2=0.8V
D5: library part CMP-0005741-4, "Diode, Zener, 11 V, 500 mW, SOD-123", Manufacturer="ON Semiconductor", Power_W=500mW, Value1=0.5W
H1: library part CMP-0067644-1, "Heatsink SOT-32, TO-220", Manufacturer="Assman WSW", Supplier Part Number 1=AE10850-ND
H2 H3 H4 H5: library part CMP-0003620-1, "Bumpon, Hemisphere, 0.44 X 0.20, Clear", Manufacturer=3M, Supplier Part Number 1=SJ5303-7-ND
J1 J2: library part CMP-0074910-1, "Terminal Block, 5.08 mm, 2x1, Brass, TH", Color=Blue, Current_A=15A, Manufacturer="On-Shore Technology", Supplier Part Number 1=ED1609-ND, Voltage_V=300V
J3: library part CMP-0054801-2, "Header, 2.54 mm, 6x1, Gold, TH", Color=Black, Manufacturer="Wurth Elektronik", Supplier Part Number 1=732-5319-ND
L1: library part CMP-0035008-1, "Power Inductors - SMD 15uH Shld 20% 22A 7.5mOhms AECQ2", Manufacturer=Coilcraft, Mouser Part Number=994-XAL1513-153MED, Operating Temperature Range=to, Self Resonant Frequency=8MHz, Test Frequency=1MHz, Tolerance_%=20%
Logo1: library part CMP-0074769-4, Manufacturer="Texas Instruments"
Logo2: library part CMP-0074847-1, "FCC_disclaimer"
Q1 Q2 Q3: library part CMP-0120049-1, "MOSFET N-Channel 200 V 80A (Tc) Surface Mount 5-SMD", Digikey Part Number=4107-EPC7020GSH-ND, Drain To Source Breakdown Voltage=200V, Input Capacitace At Vds="1313pF @ 100V", Manufacturer="EPC Space", Operating Temperature Range="-55°C to +150°C", Pulse Drain Current=200A
Q4: library part CMP-0094657-1, "Bipolar (BJT) Transistor NPN 450 V 2 A 4MHz 50 W Through Hole TO-220", Digikey Part Number=BUX85GOS-ND, Emitter Base Voltage=5V, Manufacturer="On Semiconductor", Mouser Part Number=863-BUX85G, Operating Temperature Range="-65°C to +150°C", Power_W=50W
R1: library part CMP-0022736-4, "RES, 100, 1%, 0.1 W, 0603", Manufacturer=Yageo, Power_W=100mW, Supplier Part Number 1=311-100HRCT-ND, TempCo="100 ppm/C", Tolerance_%=1%, Value2=0.1W, Value_Code=100R, ValueDisplayed=100
R2: library part CMP-0022751-4, "RES, 10.0, 1%, 0.1 W, 0603", Manufacturer=Yageo, Power_W=100mW, Supplier Part Number 1=311-10.0HRCT-ND, TempCo="100 ppm/C", Tolerance_%=1%, Value2=0.1W, Value_Code=10R0, ValueDisplayed=10.0
R3 R6 R24 R26: library part CMP-0022900-4, "RES, 1.00, 1%, 0.1 W, 0603", Manufacturer=Yageo, Power_W=100mW, Supplier Part Number 1=311-1.00HRCT-ND, TempCo="200 ppm/C", Tolerance_%=1%, Value2=0.1W, Value_Code=1R00, ValueDisplayed=1.00
R4: library part CMP-0023165-5, "RES, 511, 1%, 0.1 W, 0603", Manufacturer=Yageo, Power_W=100mW, Supplier Part Number 1=311-511HRCT-ND, TempCo="100 ppm/C", Tolerance_%=1%, Value2=0.1W, Value_Code=511R, ValueDisplayed=511
R5: library part CMP-0023142-5, "RES, 49.9 k, 1%, 0.1 W, 0603", Manufacturer=Yageo, Power_W=100mW, Supplier Part Number 1=311-49.9KHRCT-ND, TempCo="100 ppm/C", Tolerance_%=1%, Value2=0.1W, Value_Code=49k9, ValueDisplayed=49.9k
R7 R9 R18 R19 R20 R23 R29: library part CMP-0080488-1, "RES, 10.0 k, 1%, 0.1 W, 0603", Manufacturer="TT Electronics/IRC", Power_W=100mW, TempCo="100 ppm/C", Tolerance_%=1%, Value2=0.1W, Value_Code=10k0, ValueDisplayed=10.0k
R8: library part CMP-0020508-3, "RES, 27 k, 5%, 0.125 W, AEC-Q200 Grade 0, 0805", Manufacturer=Vishay-Dale, Power_W=125mW, Supplier Part Number 1=541-27KACT-ND, TempCo="200 ppm/C", Tolerance_%=5%, Value2=0.125W, Value_Code=27k0, ValueDisplayed=27k
R10: library part CMP-0023184-4, "RES, 562 k, 1%, 0.1 W, 0603", Manufacturer=Yageo, Power_W=100mW, Supplier Part Number 1=311-562KHRCT-ND, TempCo="100 ppm/C", Tolerance_%=1%, Value2=0.1W, Value_Code=562k
R11: library part CMP-0023076-5, "RES, 3.01 k, 1%, 0.1 W, 0603", Manufacturer=Yageo, Power_W=100mW, Supplier Part Number 1=311-3.01KHRCT-ND, TempCo="100 ppm/C", Tolerance_%=1%, Value2=0.1W, Value_Code=3k01, ValueDisplayed=3.01k
R12: library part CMP-0022889-5, "RES, 1.78 k, 1%, 0.1 W, 0603", Manufacturer=Yageo, Power_W=100mW, Supplier Part Number 1=311-1.78KHRCT-ND, TempCo="100 ppm/C", Tolerance_%=1%, Value2=0.1W, Value_Code=1k78, ValueDisplayed=1.78k
R13: library part CMP-0022778-5, "RES, 12.7 k, 1%, 0.1 W, 0603", Manufacturer=Yageo, Power_W=100mW, Supplier Part Number 1=311-12.7KHRCT-ND, TempCo="100 ppm/C", Tolerance_%=1%, Value2=0.1W, Value_Code=12k7, ValueDisplayed=12.7k
R14: library part CMP-0015813-2, "RES, 0.004, 1%, 1 W, 2512", Manufacturer=Panasonic, Power_W=1W, Supplier Part Number 1=P4.0MCT-ND, TempCo="350 ppm/C", Tolerance_%=1%, Value_Code=4L000, ValueDisplayed=0.004
R15: library part CMP-0022998-5, "RES, 2.80 k, 1%, 0.1 W, 0603", Manufacturer=Yageo, Power_W=100mW, Supplier Part Number 1=311-2.80KHRCT-ND, TempCo="100 ppm/C", Tolerance_%=1%, Value2=0.1W, Value_Code=2k80, ValueDisplayed=2.80k
R16: library part CMP-0022691-3, "RES, 20.0 k, 1%, 0.1 W, AEC-Q200 Grade 0, 0603", Manufacturer=Panasonic, Power_W=100mW, Supplier Part Number 1=P20.0KHCT-ND, TempCo="100 ppm/C", Tolerance_%=1%, Value2=0.1W, Value_Code=20k0, ValueDisplayed=20.0k
R17 R30: library part CMP-0023343-3, "RES, 0, 1%, 0.1 W, AEC-Q200 Grade 0, 0603", Manufacturer="Stackpole Electronics Inc", Power_W=100mW, Supplier Part Number 1=RMCF0603ZT0R00CT-ND, TempCo=ppm/C, Tolerance_%=1%, Value2=0.1W, Value_Code=0
R21: library part CMP-0023104-4, "RES, 422 k, 1%, 0.1 W, 0603", Manufacturer=Yageo, Power_W=100mW, Supplier Part Number 1=311-422KHRCT-ND, TempCo="100 ppm/C", Tolerance_%=1%, Value2=0.1W, Value_Code=422k
R22 R25: library part CMP-0022735-5, "RES, 100 k, 1%, 0.1 W, 0603", Manufacturer=Yageo, Power_W=100mW, Supplier Part Number 1=311-100KHRCT-ND, TempCo="100 ppm/C", Tolerance_%=1%, Value2=0.1W, Value_Code=100k
R27 R28: library part CMP-0015914-3, "RES, 20, 5%, 1 W, AEC-Q200 Grade 0, 2512", Manufacturer=Vishay-Dale, Power_W=1W, Supplier Part Number 1=541-20XCT-ND, TempCo="200 ppm/C", Tolerance_%=5%, Value_Code=20R0, ValueDisplayed=20
R31 R32: library part CMP-0022747-4, "RES, 10.0 M, 1%, 0.1 W, 0603", Manufacturer=Yageo, Power_W=100mW, Supplier Part Number 1=311-10.0MHRCT-ND, TempCo="100 ppm/C", Tolerance_%=1%, Value2=0.1W, Value_Code=10M0, ValueDisplayed=10.0M
R33: library part CMP-0015977-3, "RES, 51 k, 5%, 1 W, AEC-Q200 Grade 0, 2512", Manufacturer=Vishay-Dale, Power_W=1W, Supplier Part Number 1=541-51KXCT-ND, TempCo="200 ppm/C", Tolerance_%=5%, Value_Code=51k0, ValueDisplayed=51k
R34 R35: library part CMP-0015569-3, "RES, 2.00 k, 1%, 1 W, AEC-Q200 Grade 0, 2512", Manufacturer=Vishay-Dale, Power_W=1W, Supplier Part Number 1=541-2.00KAFCT-ND, TempCo="100 ppm/C", Tolerance_%=1%, Value_Code=2k00, ValueDisplayed=2.00k
R36 R37 R45: library part CMP-0023343-2, "RES, 0, 1%, 0.1 W, AEC-Q200 Grade 0, 0603", Manufacturer="Stackpole Electronics Inc", Power_W=100mW, Supplier Part Number 1=RMCF0603ZT0R00CT-ND, TempCo=ppm/C, Tolerance_%=1%, Value2=0.1W, Value_Code=0
R38 R39 R43 R44: library part CMP-0023404-3, "RES, 10.0 k, 0.1%, 0.1 W, 0603", Manufacturer="Susumu Co Ltd", Power_W=100mW, Supplier Part Number 1=RG16P10.0KBCT-ND, TempCo="25 ppm/C", Tolerance_%=0.1%, Value2=0.1W, Value_Code=10k0, ValueDisplayed=10.0k
R40 R47: library part CMP-0023920-3, "RES, 200 k, 0.1%, 0.1 W, 0603", Manufacturer="Yageo America", Power_W=100mW, TempCo="25 ppm/C", Tolerance_%=0.1%, Value2=0.1W, Value_Code=200k
R41: library part CMP-0022819-4, "RES, 15.0, 1%, 0.1 W, 0603", Manufacturer=Yageo, Power_W=100mW, Supplier Part Number 1=311-15.0HRCT-ND, TempCo="100 ppm/C", Tolerance_%=1%, Value2=0.1W, Value_Code=15R0, ValueDisplayed=15.0
R42: library part CMP-0022964-5, "RES, 274, 1%, 0.1 W, 0603", Manufacturer=Yageo, Power_W=100mW, Supplier Part Number 1=311-274HRCT-ND, TempCo="100 ppm/C", Tolerance_%=1%, Value2=0.1W, Value_Code=274R, ValueDisplayed=274
R46: library part CMP-0022989-5, "RES, 2.43 k, 1%, 0.1 W, 0603", Manufacturer=Yageo, Power_W=100mW, Supplier Part Number 1=311-2.43KHRCT-ND, TempCo="100 ppm/C", Tolerance_%=1%, Value2=0.1W, Value_Code=2k43, ValueDisplayed=2.43k
TP1 TP5 TP6 TP9 TP10: library part CMP-0055137-2, "Test Point, Miniature, Red, TH", Color=Red, Manufacturer="Keystone Electronics", Supplier Part Number 1=36-5000-ND
TP2 TP4: library part CMP-0055139-2, "Test Point, Miniature, White, TH", Color=White, Manufacturer="Keystone Electronics", Supplier Part Number 1=36-5002-ND
TP3 TP7 TP8 TP11: library part CMP-0055138-2, "Test Point, Miniature, Black, TH", Color=Black, Manufacturer="Keystone Electronics", Supplier Part Number 1=36-5001-ND
U1: library part CMP-0120202-4, Manufacturer="Texas Instruments", Operating Temperature Range=to
U2: library part CMP-0094375-1, "Radiation-Hardened 2 MHz Current Mode PWM Controllers in Space Enhanced Plastic", Manufacturer="Texas Instruments", Max Supply Voltage=14V, Min Supply Voltage=4V, Nominal Supply Current=6.25-14mA, Operating Temperature Range="-55°C to +125°C", Part Number=TPS7H5006MPWSEP, Switching Frequency=100-2000MHz
U3: library part CMP-0037180-1, "Space-enhanced-product, quad, 40-V 4.5-MHz rail-to-rail input and output operational amplifier 14-SOT-23-THIN -55 to +125", Digikey Part Number=296-OPA4H199MDYYTSEP-ND, Input Bias Current=0.00001uA, Input Offset Voltage=0.125mV, Manufacturer="Texas Instruments", Max Dual Supply Voltage=20V, Max Supply Voltage=40V, Min Dual Supply Voltage=1.35V, Min Supply Voltage=2.7V, Mouser Part Number=595-OPA4H199MDYYTSEP, Nominal Supply Current=560uA, Operating Temperature Range="-55°C to +125°C", Output Current Per Channel=75mA, Voltage Gain=145dB
U4: library part CMP-0069993-1, "3-Terminal Adjustable Regulator, 3-pin TO-39", Manufacturer="Texas Instruments", PackageTopMarking="NSZSSXXYYA 5962R99517*05VXA LM117HRLQV Q", PowerWise=N

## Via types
v1: diameter 34, hole 16, Top Layer 1 to Bottom Layer, 89 vias
v2: diameter 19.68, hole 7.87, Top Layer 1 to Bottom Layer, tented both sides, 48 vias
v3: diameter 20, hole 10, Top Layer 1 to Bottom Layer, 11 vias

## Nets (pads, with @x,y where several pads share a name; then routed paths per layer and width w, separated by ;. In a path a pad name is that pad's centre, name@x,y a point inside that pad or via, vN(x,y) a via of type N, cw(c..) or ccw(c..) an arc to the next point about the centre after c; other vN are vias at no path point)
BP5L: C21.2 R7.2 U1.33 U1.34 U1.35 | length 316.3
  Top Layer 1 w10: U1.35@2117.13,1693.71 U1.34@2117.13,1674.03 U1.33@2117.13,1654.34 2162.7,1654.34 2174.05,1642.99 2174.05,1611.5 ; R7.2@2123.04,1495.3 2124.02,1495.3 2174.05,1545.33 2174.05,1611.5 ; C21.2@2220,1611.5 2174.05,1611.5
CS+: L1.2 R14.1 R43.1 | length 212.1
  Top Layer 1 w15: R14.1@3620,2116.14 3626.77,2109.37 R43.1@3829.29,2109.37
CS-: C12.2 C13.2 C14.2 C15.2 C16.1 C17.1 C18.1 C30.1 D3.2 J2.1 R2.2 R8.1 R14.2 R38.1 TP6.1 U4.1 | length 7952.6
  Top Layer 1 w15: U4.1@1272.47,1602.15 1272.47,1677.81 1361.57,1766.91 C30.1@1361.57,1855.22 ; R2.2@2355.95,958.75 R2.2@2354.65,960.05 3649.95,960.05 3805,805 TP6.1@3805,215 ; R14.2@3620,1883.86 3711.36,1883.86 3740.39,1912.89 3740.39,2007.76 3762.07,2029.43 R38.1@3829.29,2029.43 ; v1(3988.7,2473.31) D3.2@4060.15,2473.31
  Top Layer 1 w25: R8.1@3360,1100 3486.14,1100 3526.14,1140 C14.2@3526.14,1335
  Layer 3 w15: U4.1@1272.47,1602.15 1272.47,627.53 1350,550 3470,550 TP6.1@3805,215 ; v1(3650,1600) 3804.17,1600 3988.7,1784.53 v1(3988.7,2473.31)
  other v1: 3575,1600 3575,1700 3650,1700 3575,1800 3650,1800
EN: J3.5 R10.1 R18.2 U2.8 | length 811.4
  Top Layer 1 w10: J3.5@1054.75,941.4 1241.2,941.4 1303.27,879.32 1474.85,879.32 1487.65,892.12 R10.1@1487.65,931.86 ; R10.1@1482.62,928.01 1618.04,928.01 1629.58,916.46 R18.2@1629.58,884.48 1673.19,884.48 1694.98,906.27 U2.8@1744.57,906.27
